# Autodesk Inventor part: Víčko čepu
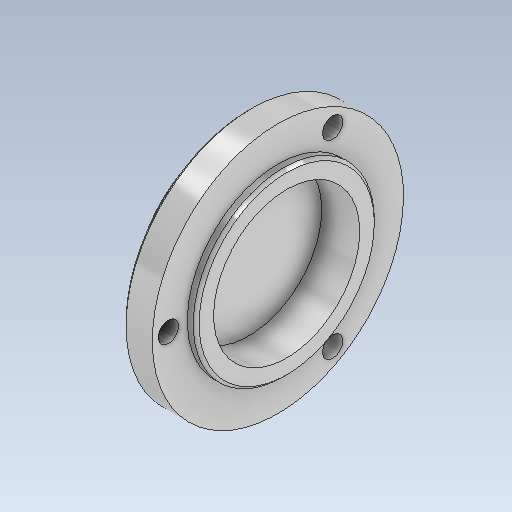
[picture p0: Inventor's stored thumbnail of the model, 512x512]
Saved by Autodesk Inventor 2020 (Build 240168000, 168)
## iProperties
Created: 2025-03
Part Number: Víčko čepu
Material: Hliník 6061
Document SubType Name: Modeling
Designer: doma
Density: 2.7 g/cm^3
Appearance: Hliník – leštěný
Mass: 177.853 g
Surface Area: 185.89 cm^2
Volume: 65.8713 cm^3
Author: doma
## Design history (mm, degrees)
sketch "Náčrt1"
  geometry: L1 (0, 0)-(-8, 0); L2 (-8, 0)-(-8, 43); L3 (-8, 43)-(10, 43); L4 (10, 43)-(10, 25); L5 (10, 25)-(0, 25); L6 (0, 25)-(0, 0); L7 (-8, 32)-(0, 32); L8 (0, 32)-(0, 43); L9 (10, 25)-(13, 25); L10 (13, 25)-(13, 31); L11 (13, 31)-(10, 31); 1 further point
  constraints: 22 end point, 7 perpendicular, 4 horizontal, 3 point on line, 1 coincident
  dimensions: "d1" = 25 distance between parallel lines of L5 L1; "d2" = 43 distance between parallel lines of L1 L3; "d3" = 8 distance of L1.start L1.end; "d6" = 11 distance of L7.end L8.end; "d7" = 8 distance of L7.start L7.end; "d8" = 31 distance between parallel lines of L1 L11; "d9" = 3 distance of L10.end L11.end; "d10" = 10 distance between parallel lines of L4 L8
revolve "Rotace1" sketch "Náčrt1" stored, may be unused: angle "d5" = 90 deg
chamfer "Zkosení1" distance "d11" = 1; stored, may be unused: second distance "d12" = 2, angle "d13" = 45 deg
chamfer "Zkosení2" distance "d14" = 1; stored, may be unused: second distance "d15" = 2, angle "d16" = 45 deg
sketch "Náčrt2"
  geometry: 4 further points
  constraints: 4 other
  dimensions: "d17" = 37.5 distance of point (0, 0) point (37.5, 0); "d20" = 360 deg dimension on point (0, 0) point (37.5, 0) (derived)
hole "Díra1" sketch "Náčrt2" at (37.5, 0), (-18.75, 32.476), (-18.75, -32.476) diameter "d22" = 7; stored, may be unused: countersink angle "d26" = 82 deg, drill point angle "d28" = 118 deg; dims "d23" = 10, "d24" = 3.023, "d25" = 2, "d27" = 7
node "Těleso1"
